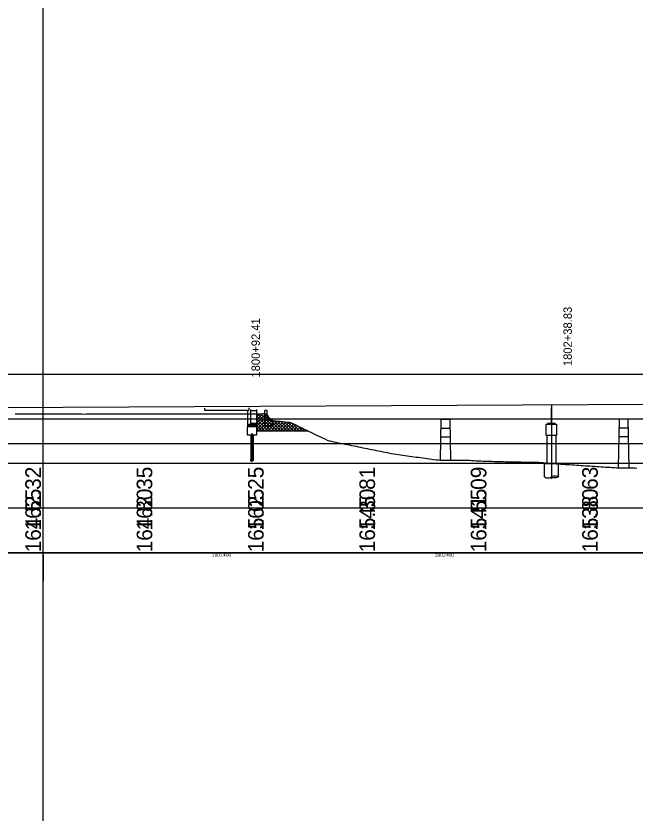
# Model space of a CAD drawing. Extents: x 2126510 to 2136144, y 865066 to 868066.
# Drawn here: x 2128456.5 to 2128734.5, y 866497 to 866854.8 of the extents above; entities that cross this region are included whole.
import ezdxf

# ---------------------------------------------------------------- set-up
doc = ezdxf.new("R2010")
doc.units = 0
for name, color, linetype in [('RD_DTM_BkLn1', 7, 'Continuous'), ('RD_EX_Bldg', 7, 'Continuous'), ('RD_EX_Bridge', 7, 'Continuous'), ('RD_EX_DR_Pipe', 7, 'Continuous'), ('RD_EX_GuardRail', 7, 'Continuous'), ('RD_EX_H2O', 7, 'Continuous'), ('RD_EX_Misc', 7, 'Continuous'), ('RD_EX_Misc_Golf_Fairway', 7, 'Continuous'), ('RD_EX_VEG', 7, 'Continuous'), ('RD_HC_Data', 7, 'Continuous'), ('RD_HC_txCode', 7, 'Continuous')]:
    doc.layers.add(name, color=color, linetype=linetype)

msp = doc.modelspace()

# ---------------------------------------------------------------- linework, layer by layer
at = {"layer": 'RD_DTM_BkLn1'}
for p, q in [((2128541.13, 866678.82), (2128541.13, 866677.82)), ((2128541.13, 866677.82), (2128561.13, 866677.92)), ((2128560.46, 866677.92), (2128560.46, 866670.48)), ((2128561.13, 866678.92), (2128561.13, 866677.92)), ((2128561.79, 866678.19), (2128561.79, 866671.49)), ((2128564.46, 866678.21), (2128564.46, 866670.62)), ((2128564.21, 866671.2), (2128560.71, 866671.2)), ((2128560.71, 866671.2), (2128560.71, 866670.62)), ((2128563.79, 866671.49), (2128561.13, 866671.49)), ((2128561.13, 866671.49), (2128561.13, 866671.2)), ((2128561.13, 866671.2), (2128563.79, 866671.2)), ((2128563.79, 866671.2), (2128563.79, 866671.49)), ((2128564.21, 866670.62), (2128564.21, 866671.2)), ((2128698.63, 866671.87), (2128695.13, 866671.87)), ((2128695.13, 866671.87), (2128695.13, 866671.54)), ((2128695.54, 866671.87), (2128698.21, 866671.87)), ((2128698.63, 866671.54), (2128698.63, 866671.87)), ((2128694.88, 866666.54), (2128694.88, 866654)), ((2128698.88, 866666.54), (2128698.88, 866654))]:
    msp.add_line(p, q, dxfattribs=at)
for points in [[(2128560.46, 866677.92), (2128561.13, 866677.92)], [(2128693.88, 866647.98), (2128693.88, 866654), (2128699.88, 866654), (2128699.88, 866647.98)]]:
    msp.add_lwpolyline(points, dxfattribs=at)
for points in [[(2128560.46, 866670.62), (2128564.46, 866670.62), (2128564.46, 866666.62), (2128560.46, 866666.62)], [(2128694.63, 866671.54), (2128699.13, 866671.54), (2128699.13, 866666.54), (2128694.63, 866666.54)]]:
    msp.add_lwpolyline(points, close=True, dxfattribs=at)
msp.add_ellipse((2128698.38, 866647.98), major_axis=(-1.5, 0), ratio=0.310397, dxfattribs=at)
msp.add_ellipse((2128695.38, 866647.98), major_axis=(-1.5, 0), ratio=0.310397, start_param=0, end_param=3.141593, dxfattribs=at)
at = {"layer": 'RD_EX_Bldg'}
for p, q in [((2128561.96, 866666.62), (2128561.96, 866655.27)), ((2128562.96, 866666.62), (2128562.96, 866655.27))]:
    msp.add_line(p, q, dxfattribs=at)
msp.add_lwpolyline([(2128563.26, 866655.27), (2128562.71, 866655.27), (2128562.71, 866655.85), (2128562.21, 866654.69), (2128562.21, 866655.27), (2128561.66, 866655.27)], dxfattribs=at)
at = {"layer": 'RD_EX_Bridge'}
for p, q in [((2128695.54, 866672.16), (2128695.54, 866671.87)), ((2128696.54, 866672.16), (2128696.54, 866671.87)), ((2128697.21, 866671.87), (2128697.21, 866672.16)), ((2128698.21, 866671.87), (2128698.21, 866672.16))]:
    msp.add_line(p, q, dxfattribs=at)
at = {"layer": 'RD_EX_DR_Pipe'}
for p, q in [((2128564.46, 866673.36), (2128567.42, 866676.33)), ((2128564.46, 866674.78), (2128565.97, 866676.29)), ((2128564.46, 866676.19), (2128564.54, 866676.28)), ((2128564.46, 866671.95), (2128568.68, 866676.17)), ((2128564.46, 866670.54), (2128569.46, 866675.53)), ((2128564.46, 866675.32), (2128571.15, 866668.62)), ((2128564.46, 866669.12), (2128569.99, 866674.65)), ((2128564.46, 866673.9), (2128569.74, 866668.62)), ((2128564.91, 866676.28), (2128572.57, 866668.62)), ((2128565.37, 866668.62), (2128570.58, 866673.83)), ((2128566.3, 866676.3), (2128573.98, 866668.62)), ((2128567.68, 866676.33), (2128575.39, 866668.62)), ((2128564.46, 866672.49), (2128568.32, 866668.62)), ((2128564.46, 866671.07), (2128566.91, 866668.62)), ((2128564.46, 866669.66), (2128565.5, 866668.62)), ((2128566.79, 866668.62), (2128571.24, 866673.07)), ((2128568.2, 866668.62), (2128572.65, 866673.07)), ((2128569.62, 866668.62), (2128574.01, 866673.01)), ((2128571.03, 866668.62), (2128575.29, 866672.88)), ((2128572.36, 866673.07), (2128576.81, 866668.62)), ((2128572.45, 866668.62), (2128576.57, 866672.75)), ((2128573.82, 866673.02), (2128578.22, 866668.62)), ((2128573.86, 866668.62), (2128577.85, 866672.61)), ((2128575.27, 866668.62), (2128579.12, 866672.47)), ((2128575.39, 866672.87), (2128579.64, 866668.62)), ((2128576.69, 866668.62), (2128580.25, 866672.18)), ((2128576.97, 866672.7), (2128581.05, 866668.62)), ((2128578.1, 866668.62), (2128581.2, 866671.72)), ((2128578.55, 866672.53), (2128582.47, 866668.62)), ((2128579.52, 866668.62), (2128582.15, 866671.26)), ((2128580.39, 866672.11), (2128583.88, 866668.62)), ((2128580.93, 866668.62), (2128583.1, 866670.79)), ((2128582.34, 866668.62), (2128584.05, 866670.33)), ((2128583.15, 866670.77), (2128585.29, 866668.62)), ((2128583.76, 866668.62), (2128585, 866669.86)), ((2128585.17, 866668.62), (2128585.95, 866669.4)), ((2128585.91, 866669.42), (2128586.71, 866668.62)), ((2128586.59, 866668.62), (2128586.9, 866668.94)), ((2128587.54, 866668.62), (2128587.19, 866668.8))]:
    msp.add_line(p, q, dxfattribs=at)
at = {"layer": 'RD_EX_GuardRail'}
for p, q in [((2131097.7, 866693.9), (2126517.45, 866693.9)), ((2128999.96, 866673.9), (2126517.45, 866673.9)), ((2131097.7, 866653.9), (2126517.45, 866653.9)), ((2131097.7, 866633.9), (2126517.45, 866633.9)), ((2131097.7, 866613.9), (2126517.45, 866613.9))]:
    msp.add_line(p, q, dxfattribs=at)
at = {"layer": 'RD_EX_H2O'}
for points in [[(2128456.19, 866676.22), (2128457.19, 866676.22), (2128458.19, 866676.22), (2128459.19, 866676.22), (2128460.19, 866676.22), (2128461.19, 866676.22), (2128462.19, 866676.22), (2128463.19, 866676.22), (2128464.19, 866676.22), (2128465.19, 866676.22), (2128466.19, 866676.22), (2128467.19, 866676.22), (2128468.19, 866676.22), (2128469.19, 866676.22), (2128470.19, 866676.22), (2128471.19, 866676.22), (2128472.19, 866676.22), (2128473.19, 866676.22), (2128474.19, 866676.22), (2128475.19, 866676.22), (2128476.19, 866676.22), (2128477.19, 866676.22), (2128478.19, 866676.22), (2128479.19, 866676.21), (2128480.19, 866676.21), (2128481.19, 866676.2), (2128482.19, 866676.19), (2128483.19, 866676.19), (2128484.19, 866676.18), (2128485.19, 866676.17), (2128486.19, 866676.17), (2128487.19, 866676.16), (2128488.19, 866676.17), (2128489.19, 866676.17), (2128490.19, 866676.17), (2128491.19, 866676.18), (2128492.19, 866676.18), (2128493.19, 866676.19), (2128494.19, 866676.19), (2128495.19, 866676.19), (2128496.19, 866676.2), (2128497.19, 866676.2), (2128498.19, 866676.2), (2128499.19, 866676.21), (2128500.19, 866676.21), (2128501.19, 866676.21), (2128502.19, 866676.22), (2128503.19, 866676.22), (2128504.19, 866676.22), (2128505.19, 866676.23), (2128506.19, 866676.23), (2128507.19, 866676.23), (2128508.19, 866676.23), (2128509.19, 866676.24), (2128510.19, 866676.24), (2128511.19, 866676.24), (2128512.19, 866676.24), (2128513.19, 866676.24), (2128514.19, 866676.24), (2128515.19, 866676.24), (2128516.19, 866676.24), (2128517.19, 866676.25), (2128518.19, 866676.25), (2128519.19, 866676.25), (2128520.19, 866676.25), (2128521.19, 866676.25), (2128522.19, 866676.25), (2128523.19, 866676.25), (2128524.19, 866676.25), (2128525.19, 866676.25), (2128526.19, 866676.25), (2128527.19, 866676.25), (2128528.19, 866676.25), (2128529.19, 866676.25), (2128530.19, 866676.25), (2128531.19, 866676.26), (2128532.19, 866676.26), (2128533.19, 866676.25), (2128534.19, 866676.25), (2128535.19, 866676.25), (2128536.19, 866676.25), (2128537.19, 866676.25)], [(2128537.19, 866676.25), (2128538.19, 866676.24), (2128539.19, 866676.24), (2128540.19, 866676.24), (2128541.19, 866676.24), (2128542.19, 866676.23), (2128543.19, 866676.23), (2128544.19, 866676.23), (2128545.19, 866676.24), (2128546.19, 866676.24), (2128547.19, 866676.24), (2128548.19, 866676.25), (2128549.19, 866676.25), (2128550.19, 866676.25), (2128551.19, 866676.25), (2128552.19, 866676.26), (2128553.19, 866676.26), (2128554.19, 866676.26), (2128555.19, 866676.26), (2128556.19, 866676.26), (2128557.19, 866676.26), (2128558.19, 866676.27), (2128559.19, 866676.27), (2128560.19, 866676.27), (2128561.19, 866676.27), (2128562.19, 866676.27), (2128563.19, 866676.28), (2128564.19, 866676.28), (2128565.19, 866676.28), (2128566.19, 866676.3), (2128567.19, 866676.32), (2128568.19, 866676.35), (2128569.19, 866675.98), (2128570.19, 866674.31), (2128571.19, 866673.07), (2128572.19, 866673.07), (2128573.19, 866673.06), (2128574.19, 866673), (2128575.19, 866672.89), (2128576.19, 866672.79), (2128577.19, 866672.68), (2128578.19, 866672.57), (2128579.19, 866672.47), (2128580.19, 866672.21), (2128581.19, 866671.73), (2128582.19, 866671.24), (2128583.19, 866670.75), (2128584.19, 866670.26), (2128585.19, 866669.77), (2128586.19, 866669.28), (2128587.19, 866668.8), (2128588.19, 866668.31), (2128589.19, 866667.82), (2128590.19, 866667.33), (2128591.19, 866666.85), (2128592.19, 866666.37), (2128593.19, 866665.9), (2128594.19, 866665.43), (2128595.19, 866664.95), (2128596.19, 866664.48), (2128597.19, 866664.16), (2128598.19, 866663.91), (2128599.19, 866663.69), (2128600.19, 866663.5), (2128601.19, 866663.3), (2128602.19, 866663.11), (2128603.19, 866662.9), (2128604.19, 866662.7), (2128605.19, 866662.49), (2128606.19, 866662.29), (2128607.19, 866662.08), (2128608.19, 866661.87), (2128609.19, 866661.67), (2128610.19, 866661.46), (2128611.19, 866661.26), (2128612.19, 866661.05), (2128613.19, 866660.85), (2128614.19, 866660.64), (2128615.19, 866660.44), (2128616.19, 866660.23), (2128617.19, 866660.03), (2128618.19, 866659.82), (2128619.19, 866659.62), (2128620.19, 866659.43), (2128621.19, 866659.23), (2128622.19, 866659.04), (2128623.19, 866658.85), (2128624.19, 866658.66), (2128625.19, 866658.47), (2128626.19, 866658.28), (2128627.19, 866658.09), (2128628.19, 866657.92), (2128629.19, 866657.78), (2128630.19, 866657.65), (2128631.19, 866657.52), (2128632.19, 866657.38), (2128633.19, 866657.25), (2128634.19, 866657.12), (2128635.19, 866656.98), (2128636.19, 866656.85), (2128637.19, 866656.72)], [(2128637.19, 866656.72), (2128638.19, 866656.58), (2128639.19, 866656.45), (2128640.19, 866656.32), (2128641.19, 866656.18), (2128642.19, 866656.05), (2128643.19, 866655.92), (2128644.19, 866655.78), (2128645.19, 866655.65), (2128646.19, 866655.55), (2128647.19, 866655.47), (2128648.19, 866655.38), (2128649.19, 866655.38), (2128650.19, 866655.38), (2128651.19, 866655.39), (2128652.19, 866655.4), (2128653.19, 866655.4), (2128654.19, 866655.41), (2128655.19, 866655.41), (2128656.19, 866655.42), (2128657.19, 866655.41), (2128658.19, 866655.4), (2128659.19, 866655.39), (2128660.19, 866655.38), (2128661.19, 866655.32), (2128662.19, 866655.25), (2128663.19, 866655.21), (2128664.19, 866655.16), (2128665.19, 866655.12), (2128666.19, 866655.07), (2128667.19, 866655.03), (2128668.19, 866655.01), (2128669.19, 866654.98), (2128670.19, 866654.93), (2128671.19, 866654.87), (2128672.19, 866654.83), (2128673.19, 866654.82), (2128674.19, 866654.8), (2128675.19, 866654.78), (2128676.19, 866654.76), (2128677.19, 866654.74), (2128678.19, 866654.73), (2128679.19, 866654.71), (2128680.19, 866654.69), (2128681.19, 866654.67), (2128682.19, 866654.66), (2128683.19, 866654.64), (2128684.19, 866654.62), (2128685.19, 866654.6), (2128686.19, 866654.59), (2128687.19, 866654.57), (2128688.19, 866654.55), (2128689.19, 866654.53), (2128690.19, 866654.52), (2128691.19, 866654.5), (2128692.19, 866654.42), (2128693.19, 866654.33), (2128694.19, 866654.24), (2128695.19, 866654.15), (2128696.19, 866654.06), (2128697.19, 866653.97), (2128698.19, 866653.9), (2128699.19, 866653.84), (2128700.19, 866653.77), (2128701.19, 866653.7), (2128702.19, 866653.64), (2128703.19, 866653.57), (2128704.19, 866653.5), (2128705.19, 866653.44), (2128706.19, 866653.37), (2128707.19, 866653.31), (2128708.19, 866653.24), (2128709.19, 866653.17), (2128710.19, 866653.11), (2128711.19, 866653.04), (2128712.19, 866652.97), (2128713.19, 866652.91), (2128714.19, 866652.84), (2128715.19, 866652.77), (2128716.19, 866652.71), (2128717.19, 866652.64), (2128718.19, 866652.57), (2128719.19, 866652.51), (2128720.19, 866652.44), (2128721.19, 866652.37), (2128722.19, 866652.31), (2128723.19, 866652.24), (2128724.19, 866652.18), (2128725.19, 866652.13), (2128726.19, 866652.08), (2128727.19, 866652.03), (2128728.19, 866651.98), (2128729.19, 866651.98), (2128730.19, 866651.99), (2128731.19, 866652), (2128732.19, 866652.01), (2128733.19, 866651.98), (2128734.19, 866651.96), (2128735.19, 866651.93)]]:
    msp.add_lwpolyline(points, dxfattribs=at)
at = {"layer": 'RD_EX_Misc'}
for p, q in [((2128468.72, 866612.9), (2128468.72, 866698.64)), ((2127961.73, 866676.62), (2129142.37, 866682.52)), ((2127368.72, 866613.9), (2131522.97, 866613.9))]:
    msp.add_line(p, q, dxfattribs=at)
msp.add_lwpolyline([(2127275.85, 866613.9), (2127275.85, 866662.9), (2131989.68, 866662.9)], dxfattribs=at)
at = {"layer": 'RD_EX_Misc_Golf_Fairway'}
for p, q in [((2128468.72, 865065.87), (2128468.72, 867928.23)), ((2128568.28, 866671.01), (2128568.28, 866677.7)), ((2128569.28, 866677.7), (2128568.28, 866677.7)), ((2128569.28, 866673.47), (2128569.28, 866677.7)), ((2128569.28, 866673.47), (2128571.78, 866673.47)), ((2128571.78, 866670.97), (2128571.78, 866673.47)), ((2128647.28, 866673.71), (2128646.9, 866655.49)), ((2128651.28, 866673.71), (2128647.28, 866673.71)), ((2128651.28, 866673.71), (2128651.67, 866655.39)), ((2128727.28, 866673.87), (2128726.83, 866652.05)), ((2128731.28, 866673.87), (2128727.28, 866673.87)), ((2128731.28, 866673.87), (2128731.74, 866652)), ((2128568.28, 866670.97), (2128571.78, 866670.97)), ((2128651.37, 866669.71), (2128647.21, 866669.71)), ((2128731.37, 866669.87), (2128727.21, 866669.87)), ((2128651.45, 866665.71), (2128647.12, 866665.71)), ((2128731.45, 866665.87), (2128727.12, 866665.87)), ((2128468.72, 866612.9), (2128468.72, 866601.12))]:
    msp.add_line(p, q, dxfattribs=at)
at = {"layer": 'RD_EX_VEG'}
msp.add_line((2128564.46, 866668.62), (2128587.64, 866668.62), dxfattribs=at)
at = {"layer": 'RD_HC_Data'}
for p, q in [((2128696.88, 866680.29), (2128696.88, 866647.1)), ((2128562.46, 866667.55), (2128562.46, 866655.27))]:
    msp.add_line(p, q, dxfattribs=at)
at = {"layer": 'RD_HC_txCode'}
for p, q in [((2128561.79, 866677.7), (2128564.46, 866677.71)), ((2128696.79, 866678.87), (2128696.79, 866672.16)), ((2128696.96, 866678.87), (2128696.96, 866672.16)), ((2128561.79, 866672.07), (2128564.46, 866672.08)), ((2128561.79, 866671.49), (2128564.46, 866671.5))]:
    msp.add_line(p, q, dxfattribs=at)

# ---------------------------------------------------------------- texts
at = {"layer": 'RD_EX_Misc'}
for s, height, p in [('1802+38.83', 3.75, (2128706.07, 866697.67)), ('1800+92.41', 3.75, (2128566.01, 866692.53)), ('162.32', 7, (2128467.72, 866623.9)), ('162.35', 7, (2128517.72, 866623.9)), ('162.25', 7, (2128567.72, 866623.9)), ('145.81', 7, (2128617.72, 866623.9)), ('141.09', 7, (2128667.72, 866623.9)), ('138.63', 7, (2128717.72, 866623.9)), ('164.55', 7, (2128467.72, 866614.05)), ('164.80', 7, (2128517.72, 866614.05)), ('165.05', 7, (2128567.72, 866614.05)), ('165.30', 7, (2128617.72, 866614.05)), ('165.55', 7, (2128667.72, 866614.05)), ('165.80', 7, (2128717.72, 866614.05))]:
    msp.add_text(s, height=height, rotation=90, dxfattribs=at).set_placement(p)
for s, p in [('1801+00', (2128544.51, 866612.1)), ('1802+00', (2128644.51, 866612.1))]:
    msp.add_text(s, height=1.6, dxfattribs=at).set_placement(p)

doc.saveas('drawing.dxf')
